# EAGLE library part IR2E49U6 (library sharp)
Current Driver IC for LED 5 sets of 7 LEDs in series Source: http://document.sharpsma.com/files/IR2E49U6.pdf
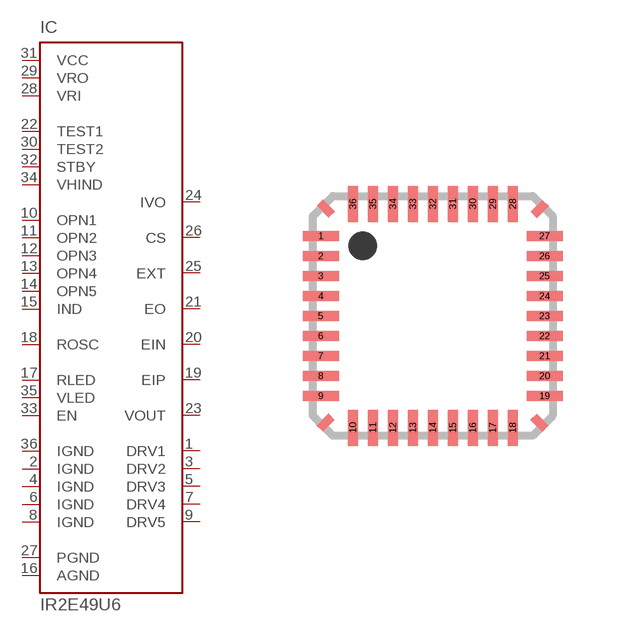
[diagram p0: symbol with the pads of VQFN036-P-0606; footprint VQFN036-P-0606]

Designator prefix IC

## IR2E49U6 (OC_FARNELL: unknown; OC_NEWARK: unknown)  [VQFN036-P-0606]
1  DRV1  out
2  IGND  pwr
3  DRV2  out
4  IGND  pwr
5  DRV3  out
6  IGND  pwr
7  DRV4  out
8  IGND  pwr
9  DRV5  out
10  OPN1  in
11  OPN2  in
12  OPN3  in
13  OPN4  in
14  OPN5  in
15  IND  in
16  AGND  pwr
17  RLED  in
18  ROSC  pas
19  EIP  pas
20  EIN  pas
21  EO  out
22  TEST1  in
23  VOUT  in
24  IVO  pas
25  EXT  out
26  CS  in
27  PGND  pwr
28  VRI  in
29  VRO  pas
30  TEST2  in
31  VCC  pwr
32  STBY  in
33  EN  in
34  VHIND  in
35  VLED  in
36  IGND  pwr

## Footprint VQFN036-P-0606 (pad centres in mm)
VQFN036-P-0606 Source: http://document.sharpsma.com/files/IR2E49U6.pdf
smd 0.9 x 0.25: 1 -2.8,2; 2 -2.8,1.5; 3 -2.8,1; 4 -2.8,0.5; 5 -2.8,0; 6 -2.8,-0.5; 7 -2.8,-1; 8 -2.8,-1.5; 9 -2.8,-2; 19 2.8,-2; 20 2.8,-1.5; 21 2.8,-1; 22 2.8,-0.5; 23 2.8,0; 24 2.8,0.5; 25 2.8,1; 26 2.8,1.5; 27 2.8,2
smd 0.25 x 0.9: 10 -2,-2.8; 11 -1.5,-2.8; 12 -1,-2.8; 13 -0.5,-2.8; 14 0,-2.8; 15 0.5,-2.8; 16 1,-2.8; 17 1.5,-2.8; 18 2,-2.8; 28 2,2.8; 29 1.5,2.8; 30 1,2.8; 31 0.5,2.8; 32 0,2.8; 33 -0.5,2.8; 34 -1,2.8; 35 -1.5,2.8; 36 -2,2.8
